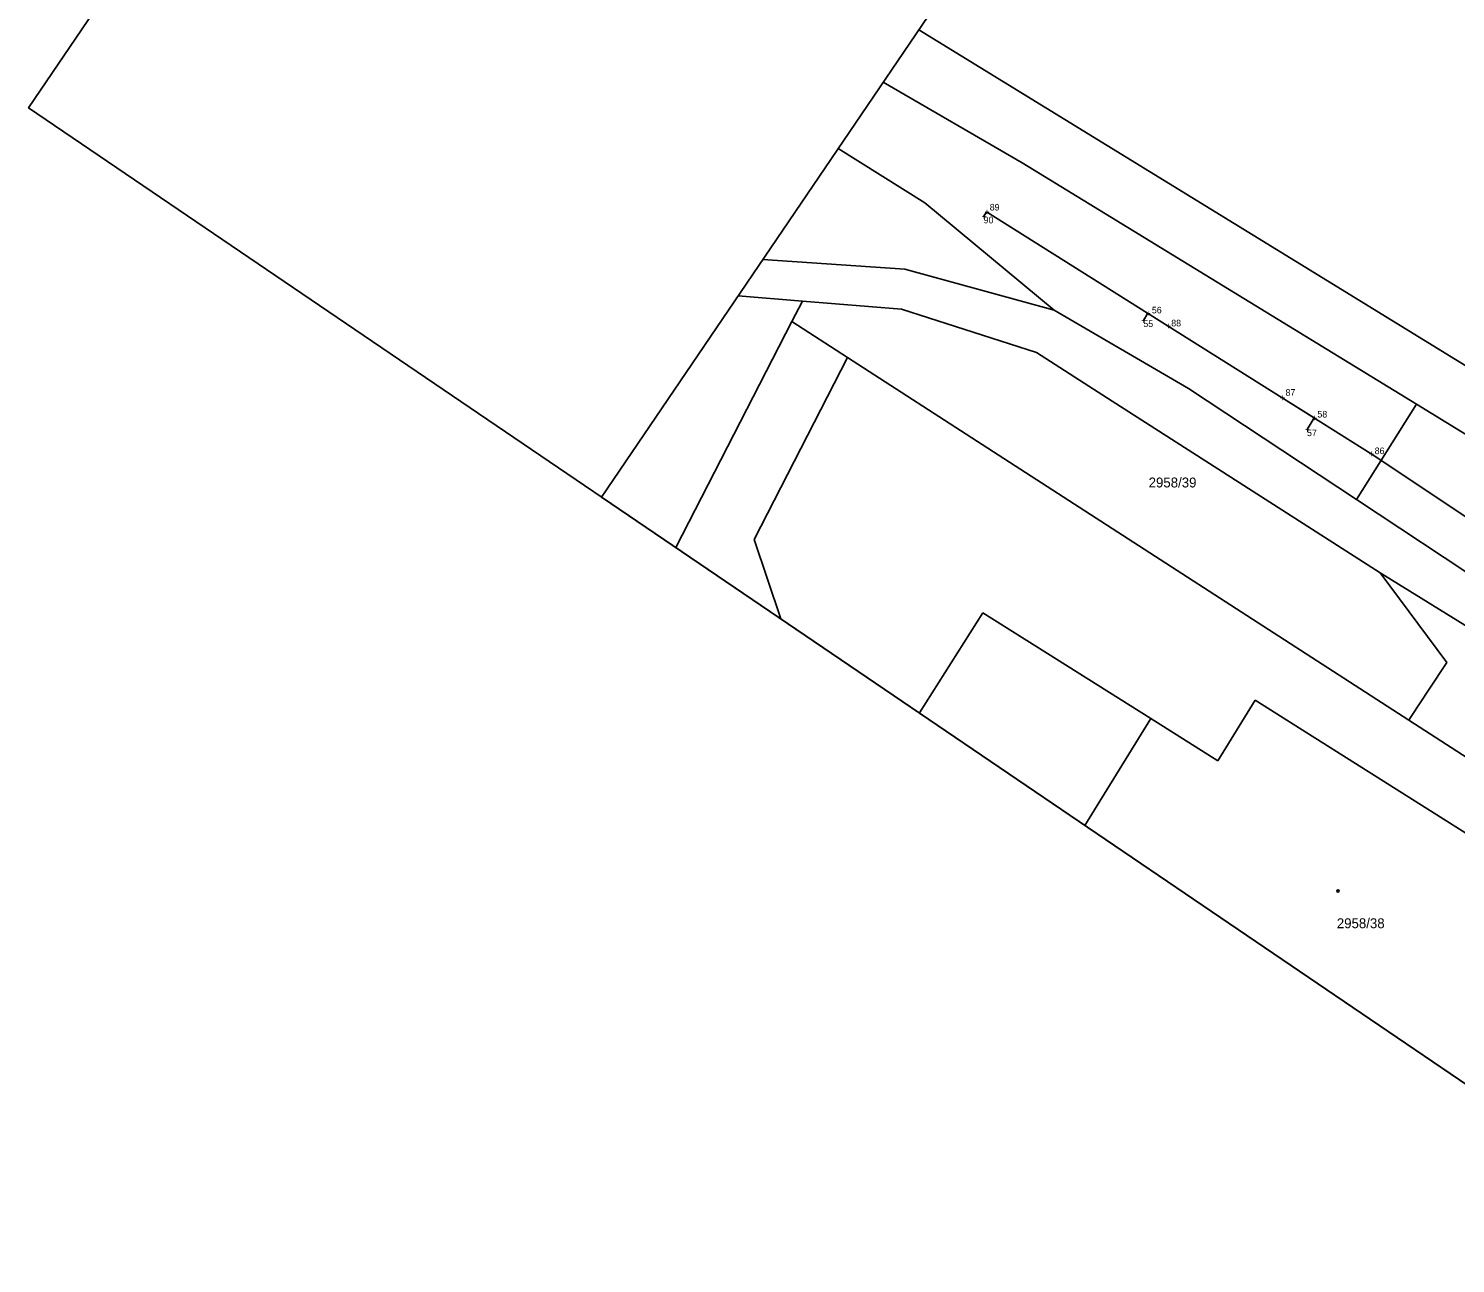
# Model space of a CAD drawing. Extents: x -621058 to -620023, y -1122866 to -1122030.
# Drawn here: x -621058.1 to -620841.8, y -1122450.9 to -1122263.7 of the extents above; entities that cross this region are included whole.
import ezdxf

# ---------------------------------------------------------------- set-up
doc = ezdxf.new("R2010")
doc.units = 0
for name, color, linetype in [('060604_ROZVODY_SEE', 7, 'Continuous'), ('BODY', 7, 'Continuous'), ('BODY POPIS', 7, 'Continuous'), ('RÁMY', 7, 'Continuous'), ('UZEMNĚNÍ', 7, 'Continuous'), ('Vrstva 53', 7, 'Continuous'), ('Vrstva 55', 7, 'Continuous'), ('Vrstva 56', 7, 'Continuous'), ('Vrstva 57', 7, 'Continuous')]:
    doc.layers.add(name, color=color, linetype=linetype)

msp = doc.modelspace()

# ---------------------------------------------------------------- linework, layer by layer
at = {"layer": '060604_ROZVODY_SEE'}
for p, q in [((-620889.11, -1122307.97), (-620888.43, -1122306.89)), ((-620864.3, -1122324.51), (-620863.2, -1122322.75))]:
    msp.add_line(p, q, dxfattribs=at)
msp.add_lwpolyline([(-620742.35, -1122414.85), (-620741.73, -1122413.88), (-620750.53, -1122408.25), (-620763.56, -1122399.82), (-620784.65, -1122386.39), (-620822.22, -1122362.42), (-620817.53, -1122355.08), (-620826.41, -1122348.08), (-620839.92, -1122337.94), (-620854.57, -1122328.18), (-620868.06, -1122319.69), (-620885.37, -1122308.82), (-620912.87, -1122291.53), (-620913.33, -1122292.25)], dxfattribs=at)
at = {"layer": 'RÁMY'}
for points in [[(-620974.7, -1122152.91), (-620106.07, -1122742.82), (-620189.51, -1122865.67), (-621058.13, -1122275.76)], [(-620887.83, -1122211.9), (-620106.07, -1122742.82), (-620189.51, -1122865.67), (-620971.26, -1122334.75)]]:
    msp.add_lwpolyline(points, close=True, dxfattribs=at)
at = {"layer": 'UZEMNĚNÍ'}
msp.add_line((-620889.11, -1122307.97), (-620888.43, -1122306.89), dxfattribs=at)
msp.add_lwpolyline([(-620864.3, -1122324.51), (-620863.2, -1122322.75), (-620868.06, -1122319.69), (-620885.37, -1122308.82), (-620912.87, -1122291.53), (-620913.33, -1122292.25)], dxfattribs=at)
at = {"layer": 'Vrstva 53'}
for p, q in [((-620928.55, -1122271.85), (-620907.48, -1122284.08)), ((-620922.25, -1122290.14), (-620935.39, -1122281.92)), ((-620902.62, -1122306.44), (-620922.25, -1122290.14)), ((-620882.26, -1122318.28), (-620902.62, -1122306.44)), ((-620856.79, -1122335.14), (-620882.26, -1122318.28)), ((-620847.72, -1122320.67), (-620838.83, -1122326.12)), ((-620821.12, -1122358.76), (-620856.79, -1122335.14))]:
    msp.add_line(p, q, dxfattribs=at)
msp.add_lwpolyline([(-620907.48, -1122284.08), (-620847.72, -1122320.67), (-620856.79, -1122335.14)], dxfattribs=at)
at = {"layer": 'Vrstva 55'}
for p, q in [((-620923.17, -1122263.93), (-620866.03, -1122298.98)), ((-620928.55, -1122271.85), (-620907.48, -1122284.08)), ((-620935.39, -1122281.92), (-620922.25, -1122290.14)), ((-620907.48, -1122284.08), (-620847.72, -1122320.67)), ((-620922.25, -1122290.14), (-620902.62, -1122306.44)), ((-620946.82, -1122298.75), (-620925.27, -1122300.21)), ((-620866.03, -1122298.98), (-620688.16, -1122408.5)), ((-620925.27, -1122300.21), (-620902.62, -1122306.44)), ((-620950.55, -1122304.25), (-620940.78, -1122305.04)), ((-620940.78, -1122305.04), (-620942.38, -1122308.15)), ((-620940.78, -1122305.04), (-620925.79, -1122306.26)), ((-620960, -1122342.4), (-620942.38, -1122308.15)), ((-620942.38, -1122308.15), (-620933.94, -1122313.6)), ((-620905.33, -1122312.86), (-620925.79, -1122306.26)), ((-620902.62, -1122306.44), (-620882.26, -1122318.28)), ((-620933.94, -1122313.6), (-620948.13, -1122341.18)), ((-620848.87, -1122368.55), (-620933.94, -1122313.6)), ((-620894.54, -1122319.77), (-620905.33, -1122312.86)), ((-620856.79, -1122335.14), (-620882.26, -1122318.28)), ((-620894.54, -1122319.77), (-620853.22, -1122346.25)), ((-620856.79, -1122335.14), (-620847.72, -1122320.67)), ((-620847.72, -1122320.67), (-620838.83, -1122326.12)), ((-620821.12, -1122358.76), (-620856.79, -1122335.14)), ((-620948.13, -1122341.18), (-620944.07, -1122353.22)), ((-620836.04, -1122356.85), (-620853.22, -1122346.25)), ((-620853.22, -1122346.25), (-620843.09, -1122359.81)), ((-620923.07, -1122367.48), (-620913.46, -1122352.29)), ((-620887.98, -1122368.3), (-620913.46, -1122352.29)), ((-620843.09, -1122359.81), (-620845.8, -1122363.88)), ((-620845.8, -1122363.88), (-620848.5, -1122367.99)), ((-620872.17, -1122365.51), (-620877.81, -1122374.71)), ((-620872.17, -1122365.51), (-620820.94, -1122397.9)), ((-620887.98, -1122368.3), (-620877.81, -1122374.71)), ((-620848.5, -1122367.99), (-620848.87, -1122368.55))]:
    msp.add_line(p, q, dxfattribs=at)
msp.add_lwpolyline([(-620804.95, -1122447.7), (-620781.81, -1122411.87), (-620848.87, -1122368.55)], dxfattribs=at)
at = {"layer": 'Vrstva 56'}
msp.add_line((-620887.98, -1122368.3), (-620897.97, -1122384.52), dxfattribs=at)
at = {"layer": 'Vrstva 57'}
msp.add_circle((-620859.6, -1122394.47), 0.175, dxfattribs=at)

# ---------------------------------------------------------------- texts
at = {"layer": 'BODY'}
for p in [(-620913.66, -1122292.75), (-620913.2, -1122292.03), (-620889.44, -1122308.47), (-620888.77, -1122307.39), (-620885.7, -1122309.32), (-620868.39, -1122320.19), (-620863.53, -1122323.25), (-620864.63, -1122325.01), (-620854.9, -1122328.68)]:
    msp.add_text('+', height=1, dxfattribs=at).set_placement(p)
at = {"layer": 'BODY POPIS'}
for s, p in [('89', (-620912.4, -1122291.31)), ('90', (-620913.33, -1122293.25)), ('56', (-620887.82, -1122306.91)), ('55', (-620889.11, -1122308.97)), ('88', (-620884.88, -1122308.88)), ('87', (-620867.56, -1122319.39)), ('58', (-620862.72, -1122322.69)), ('57', (-620864.3, -1122325.51)), ('86', (-620854.04, -1122328.24))]:
    msp.add_text(s, height=1, dxfattribs=at).set_placement(p)
at = {"layer": 'Vrstva 57'}
for s, p in [('2958/39', (-620888.31, -1122333.29)), ('2958/38', (-620859.78, -1122400.1))]:
    msp.add_text(s, height=1.5, dxfattribs=at).set_placement(p)

doc.saveas('drawing.dxf')
